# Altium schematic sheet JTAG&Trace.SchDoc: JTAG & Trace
size A4; Date: Not used; ApprovedBy: Not used; CheckedBy: Not used; Author: Not used; CompanyName: STMicroelectronics; DrawnBy: Not used; Engineer: Not used; Organization: Not used; Address1: Not used; Address2: Not used; Address3: Not used; Address4: Not used; DocumentNumber: Not used; Revision: Not used; SheetNumber: 22; SheetTotal: 23
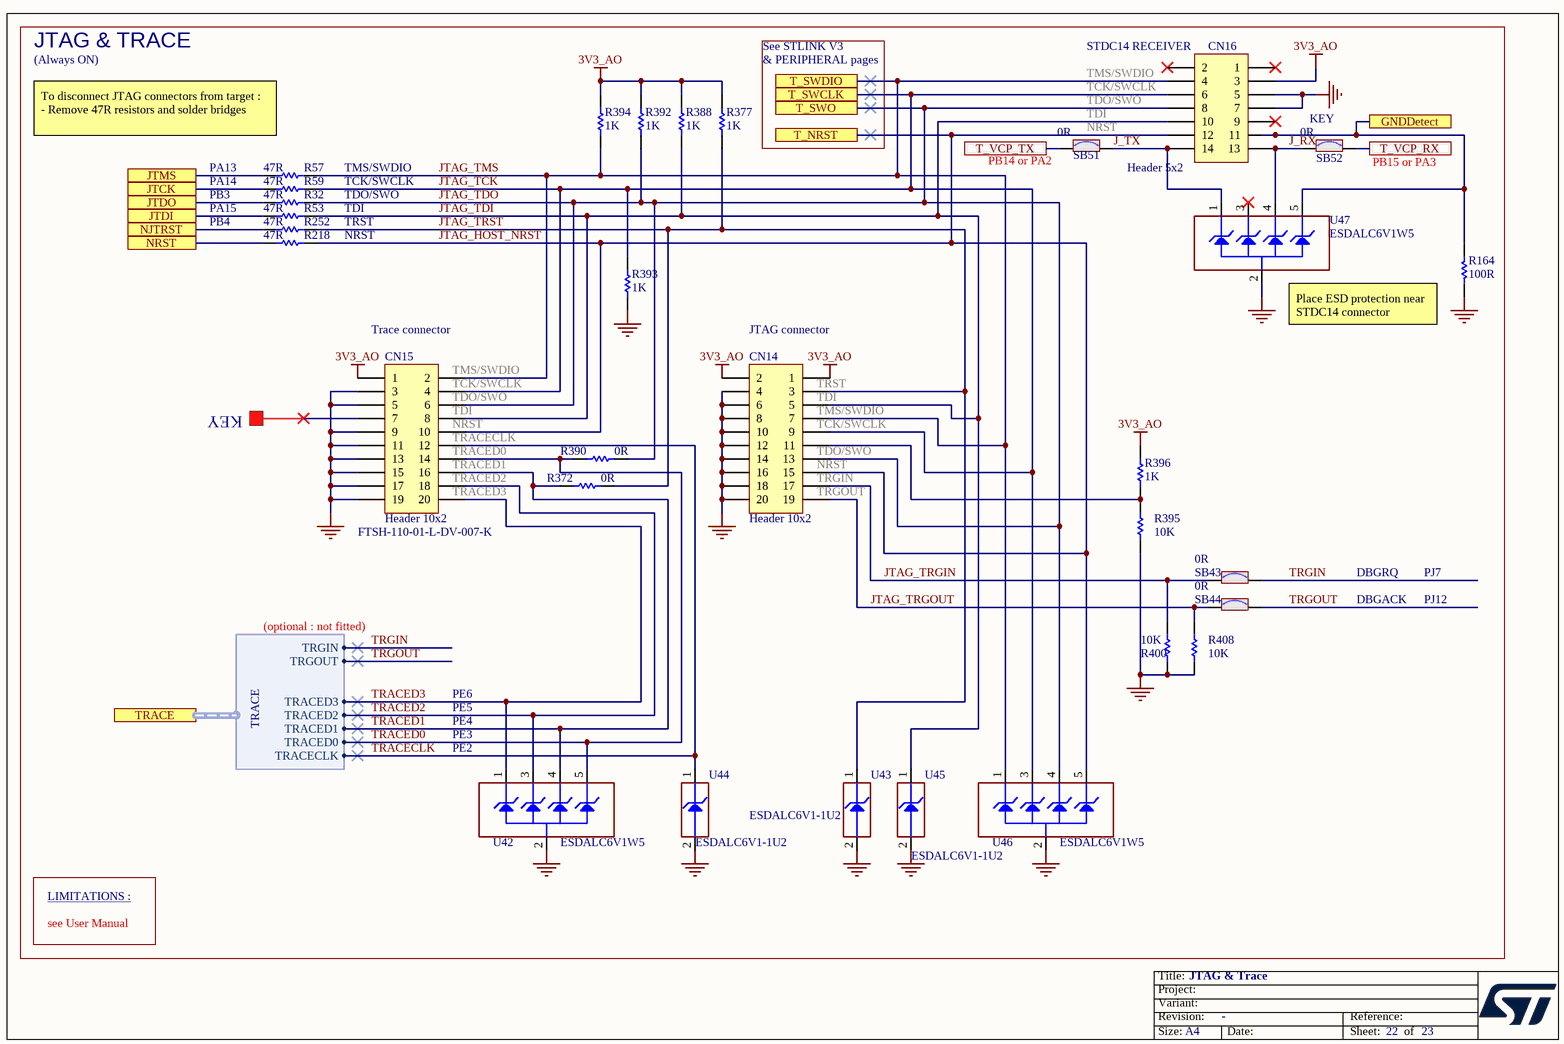
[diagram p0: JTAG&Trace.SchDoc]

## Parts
CN14  Header 10x2  [CON_CVILUX_CH87-20-2-V-1-00]
CN15  Header 10x2  [CON_SAMTEC_FTSH-110-01-L-DV]
CN16  value Header 5x2  [CON_STDC14_Receiver_MEDIUM_WITH_MIPI10_3D]  (hidden comment: Header 7x2)
R32  value 47R  [R0603]  (hidden comment: Resistor)
R53  value 47R  [R0603]  (hidden comment: Resistor)
R57  value 47R  [R0603]  (hidden comment: Resistor)
R59  value 47R  [R0603]  (hidden comment: Resistor)
R164  value 100R  [R0402]  (hidden comment: Resistor)
R218  value 47R  [R0603]  (hidden comment: Resistor)
R252  value 47R  [R0603]  (hidden comment: Resistor)
R372  value 0R  [R0402]  (hidden comment: Resistor)
R377  value 1K  [R0402]  (hidden comment: Resistor)
R388  value 1K  [R0402]  (hidden comment: Resistor)
R390  value 0R  [R0402]  (hidden comment: Resistor)
R392  value 1K  [R0402]  (hidden comment: Resistor)
R393  value 1K  [R0402]  (hidden comment: Resistor)
R394  value 1K  [R0402]  (hidden comment: Resistor)
R395  value 10K  [R0402]  (hidden comment: Resistor)
R396  value 1K  [R0402]  (hidden comment: Resistor)
R400  value 10K  [R0402]  (hidden comment: Resistor)
R408  value 10K  [R0402]  (hidden comment: Resistor)
SB43  value 0R  [SOLDER-BRIDGE_R0603-0R]  (hidden comment: SB_ON)
SB44  value 0R  [SOLDER-BRIDGE_R0603-0R]  (hidden comment: SB_ON)
SB51  value 0R  [SOLDER-BRIDGE_R0402-0R]  (hidden comment: SB_ON)
SB52  value 0R  [SOLDER-BRIDGE_R0402-0R]  (hidden comment: SB_ON)
U42  ESDALC6V1W5  [ESD_SOT323-5L]
U43  value ESDALC6V1-1U2  [ESD_ST0201]  (hidden comment: ESD-TRANSIL)
U44  value ESDALC6V1-1U2  [ESD_ST0201]  (hidden comment: ESD-TRANSIL)
U45  value ESDALC6V1-1U2  [ESD_ST0201]  (hidden comment: ESD-TRANSIL)
U46  ESDALC6V1W5  [ESD_SOT323-5L]
U47  ESDALC6V1W5  [ESD_SOT323-5L]

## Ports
GNDDetect, JTCK, JTDI, JTDO, JTMS, NJTRST, NRST, T_NRST, T_SWCLK, T_SWDIO, T_SWO, T_VCP_RX, T_VCP_TX, TRACE (harness TRACE)

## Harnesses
TRACE: TRACECLK, TRACED0, TRACED1, TRACED2, TRACED3, TRGIN, TRGOUT

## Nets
3V3_AO: CN14.1 CN14.2 CN15.1 CN16.3 R377.2 R388.2 R392.2 R394.2 R396.2
GND: CN14.4 CN14.6 CN14.8 CN14.10 CN14.12 CN14.14 CN14.16 CN14.18 CN14.20 CN15.3 CN15.5 CN15.9 CN15.11 CN15.13 CN15.15 CN15.17 CN15.19 CN16.5 CN16.7 R164.1 R393.1 R395.1 R400.1 R408.1 U42.2(GND) U43.2(GND) U44.2(GND) U45.2(GND) U46.2(GND) U47.2(GND)
GNDDetect: CN16.11 R164.2 U47.5(IO4) ; port GNDDetect
J_RX: CN16.13 SB52.1 U47.4(IO3)
J_TX: CN16.14 SB51.2 U47.1(IO1)
JTAG_HOST_NRST: CN14.15 CN15.10 CN16.12 R218.1 U46.5(IO4) ; port T_NRST
JTAG_TCK: CN14.9 CN15.4 CN16.6 R59.1 R393.2 U46.3(IO2) ; port T_SWCLK
JTAG_TDI: CN14.5 CN15.8 CN16.10 R53.1 R388.1 U45.1(IO1)
JTAG_TDO: CN14.13 CN15.6 CN16.8 R32.1 R390.2 R392.1 U46.4(IO3) ; port T_SWO
JTAG_TMS: CN14.7 CN15.2 CN16.4 R57.1 R394.1 U46.1(IO1) ; port T_SWDIO
JTAG_TRGIN: CN14.17 R400.2 SB43.1
JTAG_TRGOUT: CN14.19 R408.2 SB44.1
JTAG_TRST: CN14.3 R252.1 R372.2 R377.1 U43.1(IO1)
JTCK: R59.2 ; port JTCK
JTDI: R53.2 ; port JTDI
JTDO: R32.2 ; port JTDO
JTMS: R57.2 ; port JTMS
NJTRST: R252.2 ; port NJTRST
NRST: R218.2 ; port NRST
T_VCP_RX: SB52.2 ; port T_VCP_RX
T_VCP_TX: SB51.1 ; port T_VCP_TX
TRACECLK: CN15.12 U44.1(IO1) ; port TRACE.TRACECLK
TRACED0: CN15.14 R390.1 U42.5(IO4) ; port TRACE.TRACED0
TRACED1: CN15.16 R372.1 U42.4(IO3) ; port TRACE.TRACED1
TRACED2: CN15.18 U42.3(IO2) ; port TRACE.TRACED2
TRACED3: CN15.20 U42.1(IO1) ; port TRACE.TRACED3
TRGIN: SB43.2 ; port TRACE.TRGIN
TRGOUT: SB44.2 ; port TRACE.TRGOUT
NetCN14_11: CN14.11 R395.2 R396.1

Not connected (* = marked no-connect by the designer): CN15 7*; CN16 1* 2* 9*; U47 3(IO2)*

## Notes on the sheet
- JTAG & TRACE
- See STLINK V3
- (near CN16) STDC14 RECEIVER
- (Always ON)
- & PERIPHERAL pages
- TMS/SWDIO
- TCK/SWCLK
- (near SB51) TDO/SWO
- (near SB51) TDI
- (near SB52) KEY
- To disconnect JTAG connectors from target :
  - Remove 47R resistors and solder bridges
- PA13
- PA14
- (near SB51) PB14 or PA2
- (near SB51) NRST
- (near SB52) PB15 or PA3
- PB3
- PA15
- PB4
- TDO/SWO
- TDI
- TRST
- NRST
- (near U47) Place ESD protection near STDC14 connector
- (near CN15) Trace connector
- (near CN15) TMS/SWDIO
- (near CN15) TCK/SWCLK
- (near CN14) JTAG connector
- (near CN14) TRST
- KEY
- (near CN15) TDO/SWO
- (near CN15) TDI
- (near CN15) NRST
- (near CN15) TRACECLK
- (near CN15) TRACED0
- (near CN14) TDI
- (near CN14) TMS/SWDIO
- (near CN14) TCK/SWCLK
- (near CN14) TDO/SWO
- (near CN15) TRACED1
- (near CN15) TRACED2
- (near CN15) TRACED3
- (near CN14) NRST
- (near CN14) TRGIN
- (near CN14) TRGOUT
- (near CN15) FTSH-110-01-L-DV-007-K
- DBGRQ
- PJ7
- (optional : not fitted)
- DBGACK
- PJ12
- PE6
- PE5
- PE4
- PE3
- (near U42) PE2
- LIMITATIONS :
- see User Manual

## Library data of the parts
CN14 = MCD-01058: Header, 2.54mm, 10x2, VR, TH, Height 9.1mm/3,1mm; Part_Type: Connector; Manufacturer_Part_Number: TST-110-01-G-D; Manufacturer: SAMTEC; Alternate_Manufacturer_Part_Number: CH87-20-2-V-1-00; Alternate_Manufacturer: CVILUX; Part_Preference: Recommended; Provided_By: SUBCO; Component_Country_Of_Origin: China, Costa Rica, Malaysia, USA, Vietnam; ID: 2964; Order_Code_RS: 155-5306; ShowFields: YES
CN15 = MCD-00557: Header 10x2, 1.27mm, VR, CMS, Height 3.05mm; Part_Type: Connector; Manufacturer_Part_Number: FTSH-110-01-L-DV; Manufacturer: SAMTEC; Alternate_Manufacturer_Part_Number: P127B-2*10MGF-079-1E7A; Alternate_Manufacturer: JIUBABA; BMS_Part_Number: 9183690; Part_Preference: Recommended; Provided_By: SUBCO; Component_Country_Of_Origin: China, Costa Rica, Malaysia, USA, Vietnam; ID: 3188; Order_Code_RS: 767-6774; ShowFields: YES
CN16 = MCD-01226: Header 5x2, 1.27mm, Dual row, Straight, Surface mount, vertical male connector. 3.05mm lead. Mates with FFSD connector. Footprint compatible with FTSH-107-01-L-DV,-K,-A,-P,-ES (STDC14 MEDIUM); Manufacturer_Part_Number: FTSH-105-01-L-DV-K; Manufacturer: SAMTEC; Alternate_Manufacturer_Part_Number: P127B-2x05MGF-079-1A; Alternate_Manufacturer: JIUBABA; Part_Preference: Recommended; Partial_Alternate_Internal_Part_Number: MCD-02956, MCD-03788; Provided_By: SUBCO; Component_Country_Of_Origin: China, Costa Rica, Malaysia, USA, Vietnam; ID: 3265; Order_Code_RS: 159-2332; ShowFields: YES
R32 R53 R57 R59 R218 R252 = MCD-00482: Resistor,47R,0603,1%,1/10W; Manufacturer_Part_Number: RC0603FR-0747RL; Manufacturer: YAGEO; Part_Preference: Recommended; Provided_By: SUBCO; ECCN_US: EAR99; ECCN_EU: NEC; Component_Country_Of_Origin: China; ID: 2795; ShowFields: YES
R164 = MCD-00067: Resistor,100R,0402,1%,1/16W; Manufacturer_Part_Number: RC0402FR-07100RL; Manufacturer: YAGEO; Part_Preference: Recommended; Provided_By: SUBCO; ECCN_US: EAR99; ECCN_EU: NEC; Component_Country_Of_Origin: China; ID: 2527; Order_Code_RS: 9239111; ShowFields: YES
R372 R390 = MCD-00052: Resistor,0R,0402,5%,1/16W; Manufacturer_Part_Number: RC0402JR-070RL; Manufacturer: YAGEO; Part_Preference: Recommended; Provided_By: SUBCO; ECCN_US: EAR99; ECCN_EU: NEC; Component_Country_Of_Origin: China; ID: 2540; Order_Code_RS: 9232516RL; ShowFields: YES
R377 R388 R392-R394 R396 = MCD-00061: Resistor,1K,0402,1%,1/16W; Manufacturer_Part_Number: RC0402FR-071KL; Manufacturer: YAGEO; Part_Preference: Recommended; Provided_By: SUBCO; ECCN_US: EAR99; ECCN_EU: NEC; Component_Country_Of_Origin: China; ID: 2532; Order_Code_RS: 9239235; ShowFields: YES
R395 R400 R408 = MCD-00053: Resistor,10K,0402,1%,1/16W; Manufacturer_Part_Number: RC0402FR-0710KL; Manufacturer: YAGEO; BMS_Part_Number: 9131590; Part_Preference: Recommended; Provided_By: SUBCO; ECCN_US: EAR99; ECCN_EU: NEC; Component_Country_Of_Origin: China; ID: 2539; Order_Code_RS: 9239359; ShowFields: YES
SB43 SB44 = MCD-00071: Solder Bridge ON; Part_Type: Resistor; Manufacturer_Part_Number: RC0603JR-070RL; Manufacturer: YAGEO; Manufacturer_HQ_COO: Unknown; Part_Preference: Recommended; Provided_By: SUBCO; Component_Country_Of_Origin: China; ID: 2521; Order_Code_RS: 199-5647; ShowFields: YES
SB51 SB52 = MCD-01618: Solder Bridge 0402 ON; Part_Type: Resistor; Manufacturer_Part_Number: RC0402JR-070RL; Manufacturer: YAGEO; Part_Preference: Recommended; Provided_By: SUBCO; Component_Country_Of_Origin: China; ID: 3718; Order_Code_RS: 618-5804; ShowFields: YES
U42 U46 = MCD-00136: Dual Transil array for ESD protection; Manufacturer: STMICROELECTRONICS; Part_Type: Diode; BMS_Part_Number: 9151112; Manufacturer_HQ_COO: EU; Part_Preference: Recommended; Provided_By: SUBCO with ST control; ECCN_US: EAR99; ECCN_EU: NEC; Component_Country_Of_Origin: China; ID: 2731; Order_Code_RS: 178-7373; ShowFields: YES
U43-U45 = MCD-00170: ESD protection 6V1; Part_Type: Diode; Manufacturer: STMICROELECTRONICS; BMS_Part_Number: 9151132; Manufacturer_HQ_COO: EU; Part_Preference: Recommended; Provided_By: SUBCO with ST control; ECCN_US: EAR99; ECCN_EU: NEC; Component_Country_Of_Origin: China; ID: 2696; Order_Code_RS: 795-8404; ShowFields: YES
U47 = MCD-00136: Dual Transil array for ESD protection; Part_Type: Diode; Manufacturer: STMICROELECTRONICS; BMS_Part_Number: 9151112; Manufacturer_HQ_COO: EU; Part_Preference: Recommended; Provided_By: SUBCO with ST control; ECCN_US: EAR99; ECCN_EU: NEC; Component_Country_Of_Origin: China; ID: 2731; Order_Code_RS: 178-7373; ShowFields: YES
